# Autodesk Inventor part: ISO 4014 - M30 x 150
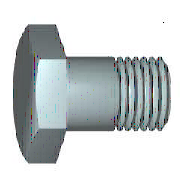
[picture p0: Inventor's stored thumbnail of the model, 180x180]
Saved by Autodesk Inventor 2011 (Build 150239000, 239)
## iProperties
Created: 2010-02
Part Number: ISO 4014 - M30 x 150
Material: Stainless Steel, 440C
Description: Hexagon head bolt - product grades A and B
Document SubType Name: Modeling
Standard: ISO 4014
Designer: 129877
Standard Revision: Third edition 1999-09-01
Standards Organization: ISO
Language: en-US
Size Designation: M30 x 150
Categories: <MemberInstance><Categories><Category DisplayName="Fasteners" InternalName="e4da775c-781d-43d5-af7c-5136215cf5a6" Mnemonic="FSTN"><Category DisplayName="Bolts"
Density: 7.75 g/cm^3
Mass: 1082.42 g
Surface Area: 205.516 cm^2
Volume: 139.667 cm^3
IsCustomPart: 0
Author: 129877
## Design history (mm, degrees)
body "Solid1"
workplane "Work Plane1"
revolve "Body" stored, may be unused: angle "d12" = 90 deg
sketch "Sketch2"
  geometry: L1 (0, 26.558)-(23, 13.279); L2 (23, 13.279)-(23, -13.279); L3 (23, -13.279)-(0, -26.558); L4 (0, -26.558)-(-23, -13.279); L5 (-23, -13.279)-(-23, 13.279); L6 (-23, 13.279)-(0, 26.558); 2 further points
  constraints: 12 end point, 1 coincident, 1 vertical, 11 other
  dimensions: "d11" = 46 distance between parallel lines of L5 L2 (= SW)
extrude "Head" join sketch "Sketch2" distance "d3" = 17.9 (= KOH - SD); taper "d4" = 0 deg
revolve "Chamfer1" stored, may be unused: angle "d21" = 90 deg
feature "Thread" dims "d15" = 72 (= GEL), "d16" = 0
chamfer "Chamfer2" distance "d6" = 2.14708 (= -0.5 x SPD + 0.5 x GD); stored, may be unused: second distance "d7" = 2.14718 (computed from GUL), angle "d55" = 45 deg
sketch "Sketch1"
  geometry: L1 (0, 21.375)-(0, 15); L2 (78, 15)-(150, 15); L3 (150, 15)-(150, 0); L4 (150, 0)-(-0.8, 0); L5 (-30.96, 0)-(180.16, 0) reference; L6 (-0.8, 0)-(-0.8, 21.375); L7 (-0.8, 21.375)-(0, 21.375); L8 (78, 15)-(75.853, 15); L9 (75.853, 15)-(0, 15); L10 (0, -4.275)-(0, 25.65) reference
  constraints: 16 end point, 2 collinear, 2 perpendicular, 1 parallel
  dimensions: "d0" = 150 distance between parallel lines of L3 L1 (= NLG); "d1" = 72 distance from line of L2.start L3 (= GEL); "d2" = 30 diameter of L2 L4 (= GD); "d9" = 0.8001 distance between parallel lines of L6 L1 (computed from SD); "d10" = 42.75 diameter of L7 L4 (= SD2); "d13" = 2.14718 distance of L2.start L8.end (computed from GAL); "d14" = 30 diameter of L9 L4 (= BDM)
sketch "Sketch4"
  geometry: L1 (-18.7, 23)-(-18.7, 26.558); L2 (-18.7, 26.558)-(-16.646, 26.558); L3 (-16.646, 26.558)-(-18.7, 23); L4 (-22.28, 0)-(2.78, 0) reference; L5 (-0.8, 26.558)-(-18.7, 26.558) reference; L6 (-18.7, 13.279)-(-18.7, 26.558) reference
  constraints: 6 end point, 2 collinear, 1 perpendicular, 1 vertical
  dimensions: "d5" = 30 deg angle of L3 L1 (= ANG1); "d19" = 46 diameter of L1.start L4 (= SW0)
other parameters: "NLG" = 150 [user parameter; used in 1 equation term], "GD" = 30 (= NND) [user parameter; used in 2 equation terms], "BDM" = 30 (= NND) [user parameter; used in 1 equation term], "KOH" = 18.7 [user parameter; used in 1 equation term], "GEL" = 72 [user parameter; used in 2 equation terms], "SW" = 46 [user parameter; used in 3 equation terms], "SW0" = 46 (= SW) [user parameter; used in 1 equation term], "SPD" = 25.70585 (= NND - 1.2269 x PTC) [user parameter; used in 1 equation term], "SD2" = 42.75 [user parameter; used in 2 equation terms], "SD" = 0.8 [user parameter; used in 2 equation terms], "ANG1" = 30 deg [user parameter; used in 1 equation term], "GAL" = 2.14708 (= 0.61345 x PTC) [user parameter; used in 1 equation term], "GUL" = 2.14708 (= 0.61345 x PTC) [user parameter; used in 1 equation term], "d8" = 0, "RR" = 1 [user parameter], "d57" = 0, "d58" = 0, "TPU" = 2.85714 (computed from PTC) [user parameter], "GD1" = 25.70585 (= THREADDIA - 1.2269 x PTC) [user parameter], "SDH" = 42.75 (= SD2) [user parameter], "TOA" = 30 deg [user parameter], "PTC" = 3.5 [user parameter; used in 5 equation terms], "E0" = 53.13 (= 1.155 x SW) [user parameter]
